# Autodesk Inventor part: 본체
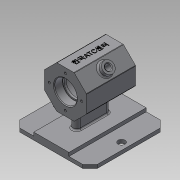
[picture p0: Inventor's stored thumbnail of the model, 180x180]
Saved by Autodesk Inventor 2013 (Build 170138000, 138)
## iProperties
Created: 2018-06
Part Number: 본체
Material: 일반
Document SubType Name: Modeling
Designer: default
Density: 1 g/cm^3
Author: default
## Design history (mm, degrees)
sketch "스케치1"
  geometry: L1 (-55, -55)-(55, -55); L2 (55, -55)-(55, 55); L3 (55, 55)-(-55, 55); L4 (-55, 55)-(-55, -55); L5 (-55, -55)-(55, 55); L6 (55, -55)-(-55, 55); 1 further point
  constraints: 12 end point, 2 midpoint, 2 parallel, 2 perpendicular, 1 horizontal
  dimensions: "d0" = 110 distance of L2.end L3.end
extrude "돌출1" new body sketch "스케치1" distance "d2" = 5; taper "d3" = 0 deg
chamfer "모따기1" distance "d4" = 10; stored, may be unused: second distance "d5" = 2, angle "d6" = 45 deg
sketch "스케치2"
  geometry: L1 (55, -45)-(55, 45) reference; L2 (45, 55)-(-45, 55) reference; L3 (-55, -25)-(55, -25); L4 (55, -25)-(55, 25); L5 (55, 25)-(-55, 25); L6 (-55, 25)-(-55, -25); L7 (-55, -25)-(55, 25); L8 (55, -25)-(-55, 25); 1 further point
  constraints: 12 end point, 2 midpoint, 2 parallel, 1 horizontal, 1 perpendicular, 1 point on line
  dimensions: "d7" = 30 distance between parallel lines of L2 L5
extrude "돌출2" join sketch "스케치2" distance "d8" = 5; taper "d9" = 0 deg
sketch "스케치3" dims "d10" = 60
  geometry: L1 (25, 10)-(25, 5) reference; L2 (25, 5)-(55, 5) reference; L3 (55, 5)-(55, 0) reference; L4 (55, 0)-(-55, 0) reference; L5 (-55, 0)-(-55, 5) reference; L6 (-55, 5)-(-25, 5) reference; L7 (-25, 5)-(-25, 10) reference; L8 (-25, 10)-(25, 10) reference; L9 (12.426, 92)-(30, 74.426); L10 (30, 74.426)-(30, 49.574); L11 (30, 49.574)-(12.426, 32); L12 (12.426, 32)-(-12.426, 32); L13 (-12.426, 32)-(-30, 49.574); L14 (-30, 49.574)-(-30, 74.426); L15 (-30, 74.426)-(-12.426, 92); L16 (-12.426, 92)-(12.426, 92); 4 further points
  constraints: 16 end point, 2 vertical alignment, 1 coincident, 1 midpoint, 1 parallel, 19 other
  dimensions: "d12" = 62 vertical distance of L4.end point (0, 62)
extrude "돌출3" join sketch "스케치3" stored distance "d13" = 70; taper "d14" = 0 deg
sketch "스케치4"
  geometry: L1 (-55, 10)-(55, 10) reference; L2 (55, 10)-(55, 0) reference; L3 (55, 0)-(-55, 0) reference; L4 (-55, 0)-(-55, 10) reference; L5 (35, 92)-(35, 32) reference; L6 (35, 32)-(-35, 32) reference; L7 (-35, 32)-(-35, 92) reference; L8 (-35, 92)-(35, 92) reference; L9 (-35, 62)-(35, 62); L10 (35, 78)-(23, 78); L11 (23, 78)-(23, 76); L12 (23, 76)-(20, 76); L13 (20, 76)-(20, 87); L14 (20, 87)-(-20, 87); L15 (-20, 87)-(-20, 76); L16 (-20, 76)-(-23, 76); L17 (-23, 76)-(-23, 78); L18 (-23, 78)-(-35, 78); 3 further points
  constraints: 20 end point, 7 parallel, 4 midpoint, 2 horizontal alignment, 2 perpendicular, 2 point on line, 1 vertical alignment
  dimensions: "d15" = 50 diameter of L14 L9; "d17" = 28 diameter of L15.end L9; "d18" = 32 diameter of L17.end L9; "d19" = 12 distance of L17.end L18.end; "d20" = 40 distance of L13.end L14.end; "d21" = 12 distance of L10.start L10.end
revolve "회전1" sketch "스케치4" stored, may be unused: angle "d22" = 90 deg
sketch "스케치5"
  geometry: C1 r 16 at (-62, 0) reference; 2 further points
  constraints: 1 vertical alignment
  dimensions: "d23" = 23 distance of C1.centre point (-62, 23)
hole "구멍1" sketch "스케치5" at (-62, 23) diameter "d24" = 3.242; stored, may be unused: countersink angle "d28" = 90 deg, drill point angle "d30" = 118 deg; dims "d25" = 8, "d26" = 4, "d27" = 2, "d29" = 10
sketch "스케치6"
  geometry: L1 (-19, -5)-(19, -5); L2 (24, 0)-(24, 0); L3 (19, 5)-(-19, 5); L4 (-24, 0)-(-24, 0); L5 (-24, -5)-(24, 5); L6 (24, -5)-(-24, 5); A1 r 5 centre (-19, 0) between (-19, 5) and (-24, 0); A2 r 5 centre (-19, 0) between (-24, 0) and (-19, -5); A3 r 5 centre (19, 0) between (19, -5) and (24, 0); A4 r 5 centre (19, 0) between (24, 0) and (19, 5); 1 further point
  constraints: 12 end point, 8 point on circle, 8 point on line, 8 tangent, 4 centre point, 3 equal radius, 2 midpoint, 2 parallel, 1 coincident, 1 horizontal, 1 perpendicular
  dimensions: "d34" = 5 radius of A1; "d35" = 38 distance of A3.centre A1.centre
extrude "돌출4" join sketch "스케치6" stored distance "d36" = 70; taper "d37" = 0 deg
sketch "스케치7"
  geometry: L1 (-45, -55)-(45, -55) reference; 2 further points
  constraints: 1 vertical alignment
  dimensions: "d38" = 10 distance from line of L1 point (0, -45)
hole "구멍2" sketch "스케치7" at (0, -45) diameter "d39" = 10; stored, may be unused: countersink angle "d43" = 90 deg, drill point angle "d45" = 118 deg; dims "d40" = 8, "d41" = 4, "d42" = 2, "d44" = 10
node "작업 평면1"
sketch "스케치8"
  geometry: L1 (70, 0)-(0, 0) reference; L2 (70, 24.853)-(70, 0) reference; L3 (70, 24.853)-(0, 24.853) reference; L4 (0, 0)-(0, 24.853) reference; C1 r 8 at (35, 12.426); 2 further points
  constraints: 1 centre point, 1 horizontal alignment, 1 midpoint, 1 vertical alignment
  dimensions: "d47" = 16 diameter of C1
extrude "돌출5" join sketch "스케치8" stored distance "d49" = 70; taper "d50" = 0 deg
sketch "스케치9"
  geometry: C1 r 8 at (0, 0) reference; C2 r 4 at (0, 0); 1 further point
  constraints: 1 centre point, 1 coincident
  dimensions: "d51" = 8 diameter of C2
extrude "돌출6" cut sketch "스케치9" stored distance "d53" = 70; taper "d54" = 0 deg
fillet "모깎기1" dims "d55" = 1
node "작업 평면2"
sketch "스케치10"
  geometry: L1 (0, -24.024)-(0, 0) reference; L2 (0, 17.695)-(70, 17.695) reference; 2 further points
  constraints: 1 other
  dimensions: "d57" = 35 distance from line of L1 point (35, -12.305); "d58" = 30 distance from line of L2 point (35, -12.305)
feature "엠보싱1" sketch "스케치10" dims "d0" = 110, "d59" = 0.5, "d60" = 0
fillet "모깎기2" dims "d61" = 0.3
fillet "모깎기3" dims "d62" = 3
chamfer "모따기2" distance "d63" = 1; stored, may be unused: second distance "d64" = 2, angle "d65" = 45 deg
fillet "모깎기4" dims "d66" = 2
node "솔리드1"
pattern_circular "원형 패턴1" dims angle "d32" = 360 deg
mirror "대칭1"
mirror "대칭2"
node "투영된 루프1"
node "절단 모서리 투영1"
node "절단 모서리 투영2"
other parameters: "d46" = 7
